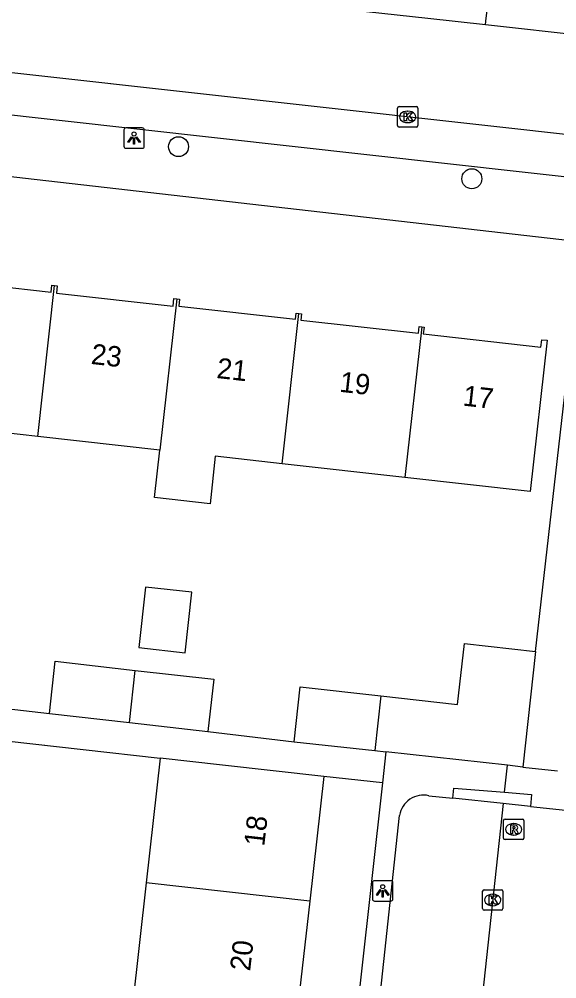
# Model space of a CAD drawing. Extents: x 161928 to 163055, y 386475 to 387428.
# Drawn here: x 162106.62 to 162132.99, y 386702.92 to 386749.95 of the extents above; entities that cross this region are included whole.
import ezdxf

# ---------------------------------------------------------------- set-up
doc = ezdxf.new("R2010")
doc.units = 0
for name, color, linetype in [('IMGEO_Boom', 7, 'Continuous'), ('IMGEO_Kolk', 7, 'Continuous'), ('IMGEO_Lichtpunt', 7, 'Continuous'), ('IMGEO_Pand', 7, 'Continuous'), ('IMGEO_Pand_nummerreeks', 7, 'Continuous'), ('IMGEO_Rijbaan_lokaal_open', 7, 'Continuous'), ('IMGEO_Rioolput', 7, 'Continuous'), ('IMGEO_Voetpad_open', 7, 'Continuous')]:
    doc.layers.add(name, color=color, linetype=linetype)

msp = doc.modelspace()

# ---------------------------------------------------------------- linework, layer by layer
at = {"layer": 'IMGEO_Boom'}
for centre in [(162114.436, 386743.706), (162128.821, 386742.132)]:
    msp.add_circle(centre, 0.489, dxfattribs=at)
at = {"layer": 'IMGEO_Kolk'}
for p, q in [((162125.177, 386744.741), (162125.177, 386745.593)), ((162125.252, 386745.667), (162126.104, 386745.667)), ((162125.665, 386745.447), (162125.69, 386745.447)), ((162126.178, 386745.593), (162126.178, 386744.741)), ((162125.688, 386744.887), (162125.663, 386744.887)), ((162126.104, 386744.667), (162125.252, 386744.667)), ((162129.422, 386707.281), (162130.274, 386707.281)), ((162129.347, 386706.355), (162129.347, 386707.207)), ((162129.835, 386707.061), (162129.86, 386707.061)), ((162130.348, 386707.207), (162130.348, 386706.355)), ((162129.858, 386706.501), (162129.833, 386706.501)), ((162130.274, 386706.281), (162129.422, 386706.281))]:
    msp.add_line(p, q, dxfattribs=at)
for points in [[(162125.177, 386744.741), (162125.177, 386745.593)], [(162125.252, 386745.667), (162126.104, 386745.667)], [(162125.498, 386745.367), (162125.621, 386745.367), (162125.621, 386745.216), (162125.751, 386745.367), (162125.915, 386745.367), (162125.769, 386745.216), (162125.922, 386744.967), (162125.77, 386744.967), (162125.685, 386745.131), (162125.621, 386745.064), (162125.621, 386744.967), (162125.498, 386744.967), (162125.498, 386745.367)], [(162126.178, 386745.593), (162126.178, 386744.741)], [(162126.104, 386744.667), (162125.252, 386744.667)], [(162129.422, 386707.281), (162130.274, 386707.281)], [(162129.347, 386706.355), (162129.347, 386707.207)], [(162129.668, 386706.981), (162129.791, 386706.981), (162129.791, 386706.83), (162129.921, 386706.981), (162130.085, 386706.981), (162129.939, 386706.83), (162130.092, 386706.581), (162129.94, 386706.581), (162129.855, 386706.745), (162129.791, 386706.678), (162129.791, 386706.581), (162129.668, 386706.581), (162129.668, 386706.981)], [(162130.348, 386707.207), (162130.348, 386706.355)], [(162130.274, 386706.281), (162129.422, 386706.281)]]:
    msp.add_lwpolyline(points, dxfattribs=at)
for centre, start, end in [((162125.254, 386745.591), 91.552, 178.448), ((162125.254, 386745.591), 91.552, 178.448), ((162126.102, 386745.591), 1.552, 88.448), ((162126.102, 386745.591), 1.552, 88.448), ((162125.254, 386744.743), 181.552, 268.448), ((162125.254, 386744.743), 181.552, 268.448), ((162126.102, 386744.743), 271.552, 358.448), ((162126.102, 386744.743), 271.552, 358.448), ((162129.424, 386707.205), 91.552, 178.448), ((162129.424, 386707.205), 91.552, 178.448), ((162130.272, 386707.205), 1.552, 88.448), ((162130.272, 386707.205), 1.552, 88.448), ((162129.424, 386706.357), 181.552, 268.448), ((162129.424, 386706.357), 181.552, 268.448), ((162130.272, 386706.357), 271.552, 358.448), ((162130.272, 386706.357), 271.552, 358.448)]:
    msp.add_arc(centre, 0.0765, start, end, dxfattribs=at)
for centre, major_axis, ratio, start_param, end_param in [((162125.664, 386745.167), (-0.387, 0.002), 0.722429, 4.712389, 7.853982), ((162125.689, 386745.167), (-0.39, 0.002), 0.717154, 1.570796, 4.712389), ((162129.834, 386706.781), (-0.387, 0.002), 0.722429, 4.712389, 7.853982), ((162129.859, 386706.781), (-0.39, 0.002), 0.717154, 1.570796, 4.712389)]:
    msp.add_ellipse(centre, major_axis=major_axis, ratio=ratio, start_param=start_param, end_param=end_param, dxfattribs=at)
at = {"layer": 'IMGEO_Lichtpunt'}
for p, q in [((162111.758, 386744.529), (162111.758, 386743.722)), ((162111.758, 386744.529), (162111.758, 386743.722)), ((162112.66, 386744.624), (162111.852, 386744.624)), ((162112.66, 386744.624), (162111.852, 386744.624)), ((162112.754, 386743.722), (162112.754, 386744.529)), ((162112.754, 386743.722), (162112.754, 386744.529)), ((162111.852, 386743.628), (162112.66, 386743.628)), ((162111.852, 386743.628), (162112.66, 386743.628)), ((162124.853, 386707.726), (162124.045, 386707.726)), ((162124.853, 386707.726), (162124.045, 386707.726)), ((162123.951, 386707.631), (162123.951, 386706.824)), ((162123.951, 386707.631), (162123.951, 386706.824)), ((162124.947, 386706.824), (162124.947, 386707.631)), ((162124.947, 386706.824), (162124.947, 386707.631)), ((162124.045, 386706.73), (162124.853, 386706.73)), ((162124.045, 386706.73), (162124.853, 386706.73))]:
    msp.add_line(p, q, dxfattribs=at)
for points in [[(162112.132, 386744.193), (162112.171, 386744.165), (162111.983, 386743.903), (162111.945, 386743.93), (162112.132, 386744.193)], [(162112.234, 386744.145), (162112.281, 386744.145), (162112.281, 386743.823), (162112.234, 386743.823), (162112.234, 386744.145)], [(162112.344, 386744.165), (162112.382, 386744.192), (162112.569, 386743.93), (162112.53, 386743.902), (162112.344, 386744.165)], [(162124.325, 386707.295), (162124.364, 386707.267), (162124.176, 386707.005), (162124.138, 386707.032), (162124.325, 386707.295)], [(162124.537, 386707.267), (162124.575, 386707.294), (162124.762, 386707.032), (162124.723, 386707.004), (162124.537, 386707.267)], [(162124.427, 386707.247), (162124.474, 386707.247), (162124.474, 386706.925), (162124.427, 386706.925), (162124.427, 386707.247)]]:
    msp.add_lwpolyline(points, dxfattribs=at)
for centre in [(162112.257, 386744.327), (162124.45, 386707.429)]:
    msp.add_circle(centre, 0.0994, dxfattribs=at)
for centre, start, end in [((162111.852, 386744.529), 90, 180), ((162111.852, 386744.529), 90, 180), ((162112.66, 386744.529), 0, 90), ((162112.66, 386744.529), 0, 90), ((162111.852, 386743.722), 180, 270), ((162111.852, 386743.722), 180, 270), ((162112.66, 386743.722), 270, 0), ((162112.66, 386743.722), 270, 360), ((162124.045, 386707.631), 90, 180), ((162124.045, 386707.631), 90, 180), ((162124.853, 386707.631), 0, 90), ((162124.853, 386707.631), 0, 90), ((162124.045, 386706.824), 180, 270), ((162124.045, 386706.824), 180, 270), ((162124.853, 386706.824), 270, 0), ((162124.853, 386706.824), 270, 360)]:
    msp.add_arc(centre, 0.0946, start, end, dxfattribs=at)
at = {"layer": 'IMGEO_Pand'}
for points in [[(162102.288, 386737.607), (162102.428, 386737.591), (162102.388, 386737.226), (162108.188, 386736.581), (162108.225, 386736.921), (162108.358, 386736.906)], [(162107.533, 386729.502), (162108.358, 386736.906)], [(162108.358, 386736.906), (162108.49, 386736.892), (162108.449, 386736.524), (162114.172, 386735.888), (162114.213, 386736.258), (162114.35, 386736.243)], [(162114.35, 386736.243), (162113.524, 386728.832)], [(162114.35, 386736.243), (162114.487, 386736.228), (162114.45, 386735.893), (162120.167, 386735.258), (162120.199, 386735.542), (162120.335, 386735.527)], [(162119.514, 386728.161), (162120.335, 386735.527)], [(162120.335, 386735.527), (162120.469, 386735.512), (162120.434, 386735.198), (162126.206, 386734.557), (162126.243, 386734.892), (162126.362, 386734.879)], [(162126.362, 386734.879), (162126.481, 386734.866), (162126.443, 386734.526), (162132.211, 386733.885), (162132.251, 386734.244), (162132.509, 386734.215), (162131.684, 386726.799), (162125.538, 386727.487)], [(162126.362, 386734.879), (162125.538, 386727.487)], [(162107.533, 386729.502), (162101.46, 386730.182)], [(162113.524, 386728.832), (162107.533, 386729.502)], [(162119.514, 386728.161), (162116.241, 386728.528), (162115.981, 386726.199), (162113.264, 386726.502), (162113.524, 386728.832)], [(162125.538, 386727.487), (162119.514, 386728.161)], [(162115.084, 386721.861), (162112.82, 386722.113), (162112.492, 386719.152), (162114.755, 386718.901), (162115.084, 386721.861)], [(162124.359, 386716.785), (162128.126, 386716.369), (162128.456, 386719.35), (162131.951, 386718.964)], [(162131.951, 386718.964), (162131.325, 386713.298)], [(162108.103, 386715.923), (162108.394, 386718.481), (162112.311, 386718.035)], [(162112.027, 386715.476), (162112.311, 386718.035)], [(162112.311, 386718.035), (162116.162, 386717.596), (162115.871, 386715.039)], [(162120.106, 386714.54), (162120.402, 386717.223), (162124.359, 386716.785)], [(162124.359, 386716.785), (162124.061, 386714.102)], [(162108.103, 386715.923), (162112.027, 386715.476)], [(162112.027, 386715.476), (162115.871, 386715.039)], [(162120.106, 386714.54), (162124.061, 386714.102)], [(162124.061, 386714.102), (162124.608, 386714.042)], [(162130.567, 386713.382), (162124.608, 386714.042)], [(162113.531, 386713.739), (162112.85, 386707.62)], [(162121.566, 386712.84), (162116.598, 386713.396), (162113.531, 386713.739)], [(162131.325, 386713.298), (162130.567, 386713.382)], [(162121.566, 386712.84), (162120.874, 386706.715)], [(162112.85, 386707.62), (162112.183, 386701.627)], [(162120.874, 386706.715), (162112.85, 386707.62)], [(162120.874, 386706.715), (162120.196, 386700.723)]]:
    msp.add_lwpolyline(points, dxfattribs=at)
at = {"layer": 'IMGEO_Rijbaan_lokaal_open'}
for points in [[(162123.662, 386750.337), (162126.661, 386750), (162129.491, 386749.686)], [(162129.491, 386749.686), (162134.473, 386749.133)], [(162135.328, 386744.09), (162086.873, 386749.474)], [(162126.717, 386711.89), (162127.894, 386711.766)], [(162130.362, 386711.505), (162127.894, 386711.766)], [(162130.362, 386711.505), (162128.996, 386698.98)], [(162118.839, 386652.858), (162124.089, 386699.955), (162125.281, 386710.926)]]:
    msp.add_lwpolyline(points, dxfattribs=at)
msp.add_arc((162126.447, 386710.741), 1.181, 76.7733, 170.9744, dxfattribs=at)
at = {"layer": 'IMGEO_Rioolput'}
for p, q in [((162130.376, 386709.818), (162130.376, 386710.67)), ((162130.451, 386710.744), (162131.303, 386710.744)), ((162131.377, 386710.67), (162131.377, 386709.818)), ((162130.864, 386710.524), (162130.889, 386710.524)), ((162131.303, 386709.744), (162130.451, 386709.744)), ((162130.887, 386709.964), (162130.862, 386709.964))]:
    msp.add_line(p, q, dxfattribs=at)
for points in [[(162130.376, 386709.818), (162130.376, 386710.67)], [(162130.451, 386710.744), (162131.303, 386710.744)], [(162131.377, 386710.67), (162131.377, 386709.818)], [(162130.965, 386710.442), (162130.713, 386710.444), (162130.713, 386710.044)], [(162130.713, 386710.044), (162130.837, 386710.044), (162130.837, 386710.206), (162130.848, 386710.206)], [(162130.891, 386710.363), (162130.837, 386710.363), (162130.837, 386710.282)], [(162130.837, 386710.282), (162130.889, 386710.282)], [(162130.895, 386710.177), (162130.966, 386710.044), (162131.106, 386710.044), (162131.041, 386710.17)], [(162131.303, 386709.744), (162130.451, 386709.744)]]:
    msp.add_lwpolyline(points, dxfattribs=at)
for centre, radius, start, end in [((162130.453, 386710.668), 0.0765, 91.552, 178.448), ((162130.453, 386710.668), 0.0765, 91.552, 178.448), ((162131.301, 386710.668), 0.0765, 1.552, 88.448), ((162131.301, 386710.668), 0.0765, 1.552, 88.448), ((162130.847, 386710.153), 0.0533, 26.0293, 88.6989), ((162130.873, 386710.471), 0.19, 274.7715, 282.9687), ((162130.897, 386710.267), 0.0964, 77.0061, 93.1865), ((162130.911, 386710.324), 0.0378, 276.6634, 79.6772), ((162130.964, 386710.332), 0.109, 350.3612, 89.416), ((162130.962, 386710.332), 0.112, 277.5842, 350.9817), ((162130.946, 386710.117), 0.108, 29.5134, 73.7905), ((162130.453, 386709.82), 0.0765, 181.552, 268.448), ((162130.453, 386709.82), 0.0765, 181.552, 268.448), ((162131.301, 386709.82), 0.0765, 271.552, 358.448), ((162131.301, 386709.82), 0.0765, 271.552, 358.448)]:
    msp.add_arc(centre, radius, start, end, dxfattribs=at)
for centre, major_axis, ratio, start_param, end_param in [((162130.863, 386710.244), (-0.387, 0.002), 0.722429, 4.712389, 7.853982), ((162130.888, 386710.244), (-0.39, 0.002), 0.717154, 1.570796, 4.712389)]:
    msp.add_ellipse(centre, major_axis=major_axis, ratio=ratio, start_param=start_param, end_param=end_param, dxfattribs=at)
at = {"layer": 'IMGEO_Voetpad_open'}
for points in [[(162129.491, 386749.686), (162129.532, 386750), (162129.629, 386750.754), (162134.53, 386750.22), (162134.518, 386750), (162134.473, 386749.133)], [(162135.098, 386742.034), (162089.818, 386747.087)], [(162134.239, 386739.027), (162084.608, 386744.686)], [(162131.951, 386718.964), (162134.239, 386739.027)], [(162103.836, 386716.407), (162108.103, 386715.923)], [(162101.941, 386712.722), (162102.186, 386715.002), (162113.531, 386713.739)], [(162115.871, 386715.039), (162120.106, 386714.54)], [(162124.608, 386714.042), (162124.438, 386712.52)], [(162130.423, 386712.063), (162130.567, 386713.382)], [(162131.325, 386713.298), (162133.024, 386713.116)], [(162124.438, 386712.52), (162119.067, 386664.312)], [(162124.438, 386712.52), (162121.566, 386712.84)], [(162127.894, 386711.766), (162127.934, 386712.264), (162130.423, 386712.063)], [(162130.423, 386712.063), (162131.756, 386711.955), (162131.706, 386711.363)], [(162131.706, 386711.363), (162130.362, 386711.505)], [(162131.706, 386711.363), (162135.45, 386710.968)]]:
    msp.add_lwpolyline(points, dxfattribs=at)

# ---------------------------------------------------------------- texts
at = {"layer": 'IMGEO_Pand_nummerreeks'}
for s, rotation, p in [('23', 353.6138, (162110.113, 386733.059)), ('21', 353.6115, (162116.274, 386732.369)), ('19', 353.6138, (162122.301, 386731.694)), ('17', 353.6138, (162128.349, 386731.017)), ('18', 83.5512, (162118.639, 386709.383)), ('20', 83.5512, (162117.948, 386703.267))]:
    msp.add_text(s, height=1, rotation=rotation, dxfattribs=at).set_placement(p)

doc.saveas('drawing.dxf')
